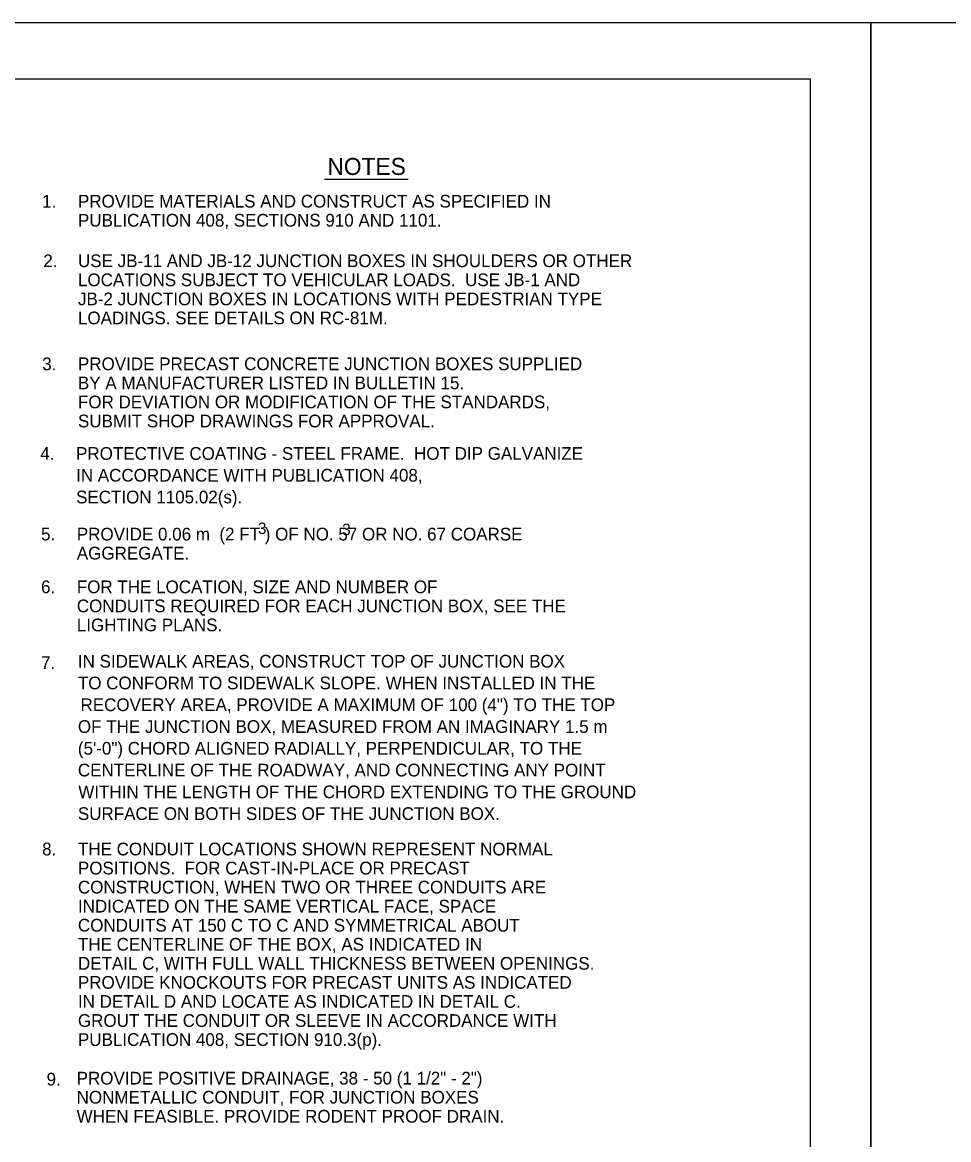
# Model space of a CAD drawing. Extents: x 638455 to 640199, y 298558 to 299152.
# Drawn here: x 639071.2 to 639316.2, y 298856.7 to 299152.2 of the extents above; entities that cross this region are included whole.
import ezdxf

# ---------------------------------------------------------------- set-up
doc = ezdxf.new("R2010")
doc.units = 0
for name, color, linetype in [('1', 7, 'Continuous'), ('2', 7, 'Continuous'), ('3', 7, 'Continuous'), ('PLT-BNDY', 7, 'Continuous')]:
    doc.layers.add(name, color=color, linetype=linetype)

msp = doc.modelspace()

# ---------------------------------------------------------------- linework, layer by layer
at = {"layer": '1'}
msp.add_lwpolyline([(639279.61, 298573.25), (639279.61, 299137.25), (638493.61, 299137.25), (638493.61, 298573.25), (639279.61, 298573.25), (639279.61, 298599.61), (639079.61, 298599.61), (639079.61, 298664.29), (639279.61, 298664.29), (639279.61, 298693.25), (639079.61, 298693.25), (639079.61, 298573.25), (639158.42, 298573.25), (639158.42, 298599.61), (639158.42, 298573.25), (639235.42, 298573.25), (639235.42, 298599.61), (639235.42, 298587.29), (639279.61, 298587.29)], dxfattribs=at)
at = {"layer": '3'}
msp.add_line((639151.17, 299110.78), (639173.29, 299110.78), dxfattribs=at)
at = {"layer": 'PLT-BNDY'}
for points in [[(638454.61, 299152.25), (639295.61, 299152.25), (639295.61, 298558.25), (638454.61, 298558.25)], [(639295.61, 299152.25), (640136.61, 299152.25), (640136.61, 298558.25), (639295.61, 298558.25)]]:
    msp.add_lwpolyline(points, close=True, dxfattribs=at)

# ---------------------------------------------------------------- texts
at = {"layer": '2'}
for s, p in [('PROTECTIVE COATING - STEEL FRAME.  HOT DIP GALVANIZE', (639085.44, 299036.53)), ('IN ACCORDANCE WITH PUBLICATION 408,', (639085.44, 299030.77)), ('SECTION 1105.02(s).', (639085.44, 299025.01)), ('IN SIDEWALK AREAS, CONSTRUCT TOP OF JUNCTION BOX', (639085.92, 298981.58)), ('TO CONFORM TO SIDEWALK SLOPE. WHEN INSTALLED IN THE', (639085.92, 298975.82)), ('RECOVERY AREA, PROVIDE A MAXIMUM OF 100 (4") TO THE TOP', (639086.61, 298970.06)), ('OF THE JUNCTION BOX, MEASURED FROM AN IMAGINARY 1.5 m', (639085.92, 298964.3)), ('(5\'-0") CHORD ALIGNED RADIALLY, PERPENDICULAR, TO THE', (639085.92, 298958.54)), ('CENTERLINE OF THE ROADWAY, AND CONNECTING ANY POINT', (639085.92, 298952.78)), ('WITHIN THE LENGTH OF THE CHORD EXTENDING TO THE GROUND', (639086.02, 298947.02)), ('SURFACE ON BOTH SIDES OF THE JUNCTION BOX.', (639085.92, 298941.26)), ('PROVIDE POSITIVE DRAINAGE, 38 - 50 (1 1/2" - 2") ', (639085.59, 298871.29)), ('NONMETALLIC CONDUIT, FOR JUNCTION BOXES ', (639085.59, 298866.25)), ('WHEN FEASIBLE. PROVIDE RODENT PROOF DRAIN.', (639085.59, 298861.21))]:
    msp.add_text(s, height=3.36, dxfattribs=at).set_placement(p)
at = {"layer": '3'}
for s, height, p in [('NOTES', 4.5, (639151.91, 299111.88)), ('1.  ', 3.36, (639076.48, 299103.26)), ('PROVIDE MATERIALS AND CONSTRUCT AS SPECIFIED IN', 3.36, (639085.94, 299103.26)), ('PUBLICATION 408, SECTIONS 910 AND 1101.', 3.36, (639085.94, 299098.22)), ('2.  ', 3.36, (639076.77, 299087.49)), ('USE JB-11 AND JB-12 JUNCTION BOXES IN SHOULDERS OR OTHER', 3.36, (639085.94, 299087.5)), ('LOCATIONS SUBJECT TO VEHICULAR LOADS.  USE JB-1 AND', 3.36, (639085.94, 299082.46)), ('JB-2 JUNCTION BOXES IN LOCATIONS WITH PEDESTRIAN TYPE', 3.36, (639085.94, 299077.42)), ('LOADINGS. SEE DETAILS ON RC-81M.', 3.36, (639085.94, 299072.38)), ('3.  ', 3.36, (639076.48, 299060.24)), ('PROVIDE PRECAST CONCRETE JUNCTION BOXES SUPPLIED', 3.36, (639085.94, 299060.24)), ('BY A MANUFACTURER LISTED IN BULLETIN 15.', 3.36, (639085.94, 299055.2)), ('FOR DEVIATION OR MODIFICATION OF THE STANDARDS,', 3.36, (639085.94, 299050.16)), ('SUBMIT SHOP DRAWINGS FOR APPROVAL.', 3.36, (639085.94, 299045.12)), ('4.  ', 3.36, (639075.97, 299036.53)), ('5.  ', 3.36, (639076.18, 299015.2)), ('PROVIDE 0.06 m  (2 FT ) OF NO. 57 OR NO. 67 COARSE', 3.36, (639085.64, 299015.2)), ('3', 3.03, (639133.52, 299016.9)), ('3', 3.03, (639155.79, 299016.6)), ('AGGREGATE.', 3.36, (639085.64, 299010.16)), ('6.  ', 3.36, (639076.18, 299001.25)), ('FOR THE LOCATION, SIZE AND NUMBER OF', 3.36, (639085.64, 299001.25)), ('CONDUITS REQUIRED FOR EACH JUNCTION BOX, SEE THE', 3.36, (639085.64, 298996.21)), ('LIGHTING PLANS.', 3.36, (639085.64, 298991.17)), ('7.  ', 3.36, (639076.18, 298981.16)), ('8.  ', 3.36, (639076.46, 298931.9)), ('THE CONDUIT LOCATIONS SHOWN REPRESENT NORMAL', 3.36, (639085.93, 298931.9)), ('POSITIONS.  FOR CAST-IN-PLACE OR PRECAST', 3.36, (639085.93, 298926.86)), ('CONSTRUCTION, WHEN TWO OR THREE CONDUITS ARE', 3.36, (639085.93, 298921.82)), ('INDICATED ON THE SAME VERTICAL FACE, SPACE', 3.36, (639085.93, 298916.78)), ('CONDUITS AT 150 C TO C AND SYMMETRICAL ABOUT', 3.36, (639085.93, 298911.74)), ('CONDUITS AT 150 C', 3.36, (639085.93, 298911.74)), ('THE CENTERLINE OF THE BOX, AS INDICATED IN', 3.36, (639085.93, 298906.7)), ('DETAIL C, WITH FULL WALL THICKNESS BETWEEN OPENINGS. ', 3.36, (639085.93, 298901.66)), ('PROVIDE KNOCKOUTS FOR PRECAST UNITS AS INDICATED', 3.36, (639085.93, 298896.62)), ('PRO', 3.36, (639085.93, 298896.62)), ('IN DETAIL D AND LOCATE AS INDICATED IN DETAIL C.', 3.36, (639085.93, 298891.58)), ('GROUT THE CONDUIT OR SLEEVE IN ACCORDANCE WITH', 3.36, (639085.93, 298886.54)), ('PUBLICATION 408, SECTION 910.3(p).', 3.36, (639085.93, 298881.5)), ('9.  ', 3.36, (639077.64, 298871.02))]:
    msp.add_text(s, height=height, dxfattribs=at).set_placement(p)

doc.saveas('drawing.dxf')
